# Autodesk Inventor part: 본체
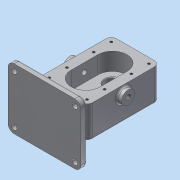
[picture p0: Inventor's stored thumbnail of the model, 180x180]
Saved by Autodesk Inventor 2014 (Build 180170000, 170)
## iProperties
Created: 2026-10
Part Number: 본체
Material: 알루미늄 6061
Document SubType Name: Modeling
Designer: dg
Density: 2.71 g/cm^3
Appearance: 알루미늄 - 평지
Mass: 1478.46 g
Surface Area: 818.031 cm^2
Volume: 545.557 cm^3
Author: dg
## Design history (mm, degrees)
sketch "스케치1"
  geometry: L1 (-40, 60)-(40, 60); L2 (40, 60)-(40, -60); L3 (40, -60)-(-40, -60); L4 (-40, -60)-(-40, 60); 3 further points
  constraints: 8 end point, 2 midpoint, 2 parallel, 1 horizontal, 1 horizontal alignment, 1 perpendicular, 1 vertical alignment
  dimensions: "d0" = 80 distance of L1.start L1.end; "d1" = 120 distance of L1.end L2.end
extrude "돌출1" new body sketch "스케치1" stored distance "d2" = 53; taper "d3" = 0 deg
sketch "스케치2"
  geometry: L1 (-40, 60)-(-40, -60) reference; L2 (0, 22)-(0, -22); L3 (-24, 22)-(-24, -22); L4 (24, -22)-(24, 22); A1 r 24 centre (0, 22) between (24, 22) and (-24, 22); A2 r 24 centre (0, -22) between (-24, -22) and (24, -22); 2 further points
  constraints: 8 end point, 4 point on circle, 4 tangent, 2 centre point, 2 parallel, 1 coincident, 1 midpoint
  dimensions: "d4" = 48 distance between parallel lines of L4 L3; "d5" = 44 distance of L4.start L4.end
extrude "돌출2" cut sketch "스케치2" distance "d6" = 29; taper "d7" = 0 deg
node "작업 평면1"
sketch "스케치3"
  geometry: L1 (-20, 70)-(100, 70); L2 (100, 70)-(100, -30); L3 (100, -30)-(-20, -30); L4 (-20, -30)-(-20, 70); L5 (0, 53)-(80, 53) reference; L6 (0, 53)-(0, 0) reference; L7 (80, 0)-(0, 0) reference; L8 (80, 0)-(80, 53) reference; L9 (0, 53)-(80, 53) reference; 1 further point
  constraints: 8 end point, 2 parallel, 1 horizontal, 1 perpendicular
  dimensions: "d9" = 100 distance of L3.end L1.start; "d10" = 120 distance of L2.end L3.end; "d25" = 17 distance between parallel lines of L1 L5; "d26" = 20 distance between parallel lines of L2 L8
extrude "돌출3" join sketch "스케치3" distance "d11" = 10; taper "d12" = 0 deg
sketch "스케치4"
  geometry: L1 (-60, 26.5)-(-60, -26.5) reference; L2 (-80, -43.5)-(-80, 56.5) reference; L3 (-57, 13.221)-(-80, 26.5); L4 (-57, -13.221)-(-80, -26.5); L5 (-57, 13.221)-(-57, -13.221); L6 (-80, 26.5)-(-80, -26.5); 3 further points
  constraints: 8 end point, 2 horizontal alignment, 2 midpoint, 2 point on line, 1 collinear, 1 parallel
  dimensions: "d13" = 53 distance of L4.end L3.end; "d14" = 60 deg angle of L2 L3; "d15" = 3 distance between parallel lines of L5 L1
extrude "돌출4" join sketch "스케치4" stored distance "d16" = 48; taper "d17" = 0 deg
sketch "스케치5"
  geometry: A1 r 24 centre (0, -22) between (-24, -22) and (24, -22) reference; A2 r 24 centre (0, 22) between (24, 22) and (-24, 22) reference; 1 further point
hole "구멍1" sketch "스케치5" at (0, 22), (0, -22) diameter "d18" = 25; stored, may be unused: countersink angle "d22" = 90 deg, drill point angle "d24" = 0 deg; dims "d19" = 6, "d20" = 4, "d21" = 2, "d23" = 15
sketch "스케치6"
  geometry: C1 r 12.5 at (0, 22) reference; C2 r 19 at (0, 22); 1 further point
  constraints: 1 centre point, 1 coincident
  dimensions: "d27" = 38 diameter of C2
extrude "돌출5" join sketch "스케치6" distance "d28" = 17; taper "d29" = 0 deg
sketch "스케치7"
  geometry: C1 r 19 at (0, 0) reference; 1 further point
hole "구멍2" sketch "스케치7" at (0, 0) diameter "d30" = 17; stored, may be unused: countersink angle "d34" = 90 deg, drill point angle "d36" = 0 deg; dims "d31" = 6, "d32" = 28, "d33" = 7.3, "d35" = 15
sketch "스케치8"
  geometry: L1 (0, 0)-(0, 120) reference; L2 (70, -30)-(-30, -30) reference; C1 r 11 at (14, 60); 1 further point
  constraints: 1 centre point
  dimensions: "d37" = 14 distance from line of L1 C1.centre; "d38" = 22 diameter of C1; "d39" = 90 distance from line of L2 C1.centre
extrude "돌출6" join sketch "스케치8" distance "d40" = 8; taper "d41" = 0 deg
sketch "스케치9"
  geometry: C1 r 11 at (-14, 60) reference; C2 r 11 at (-14, 60); 1 further point
  constraints: 1 centre point, 1 coincident, 1 concentric
extrude "돌출7" join sketch "스케치9" distance "d42" = 8; taper "d43" = 0 deg
hole "구멍3" diameter "d46" = 8; stored, may be unused: countersink angle "d52" = 90 deg, drill point angle "d54" = 118 deg; dims "d44" = 10, "d45" = 10, "d47" = 9, "d48" = 0.62479, "d49" = 7.985, "d50" = 28, "d51" = 7.3, "d53" = 30
hole "구멍4" diameter "d57" = 8; stored, may be unused: countersink angle "d63" = 90 deg, drill point angle "d65" = 118 deg; dims "d55" = 10, "d56" = 10, "d58" = 9, "d59" = 0.62479, "d60" = 7.985, "d61" = 28, "d62" = 7.3, "d64" = 30
sketch "스케치10"
  geometry: A1 r 24 centre (0, -22) between (-24, -22) and (24, -22) reference; A2 r 24 centre (0, 22) between (24, 22) and (-24, 22) reference; 9 further points
  constraints: 6 horizontal alignment, 6 vertical alignment
  dimensions: "d66" = 62 distance of point (31, 51) point (-31, 51); "d67" = 29 distance of point (-31, 22) point (-31, 51); "d68" = 29 distance of point (-31, -51) point (-31, -22); "d69" = 31 horizontal distance of A1.centre point (-31, -51)
hole "구멍5" sketch "스케치10" at (-31, 51), (-31, 22), (31, 22), (31, 51), (31, -22), (-31, -22), (-31, -51), (31, -51) diameter "d70" = 4.134; stored, may be unused: countersink angle "d74" = 90 deg, drill point angle "d76" = 118 deg; dims "d71" = 10, "d72" = 28, "d73" = 7.3, "d75" = 12
fillet "모깎기1" dims "d77" = 10
sketch "스케치11"
  geometry: A1 r 10 centre (-10, 60) between (-10, 70) and (-20, 60) reference; A2 r 10 centre (-10, -20) between (-20, -20) and (-10, -30) reference; A3 r 10 centre (90, -20) between (90, -30) and (100, -20) reference; A4 r 10 centre (90, 60) between (100, 60) and (90, 70) reference; 1 further point
hole "구멍6" sketch "스케치11" at (-10, 60), (-10, -20), (90, -20), (90, 60) diameter "d78" = 9; stored, may be unused: countersink angle "d82" = 82 deg, drill point angle "d84" = 0 deg; dims "d79" = 10, "d80" = 3.023, "d81" = 7.3, "d83" = 12
chamfer "모따기1" distance "d85" = 0.7; stored, may be unused: second distance "d86" = 2, angle "d87" = 30 deg
fillet "모깎기2" dims "d88" = 0.5
fillet "모깎기3" dims "d89" = 9
fillet "모깎기4" dims "d90" = 3
fillet "모깎기5" dims "d91" = 3
chamfer "모따기2" distance "d92" = 1; stored, may be unused: second distance "d93" = 2, angle "d94" = 30 deg
sketch "스케치12"
  geometry: L1 (-10, -30)-(90, -30) reference; 2 further points
  constraints: 1 vertical alignment, 1 other
  dimensions: "d95" = 10 distance from line of L1 point (40, -20)
feature "엠보싱1" sketch "스케치12" dims "d0" = 80, "d1" = 120, "d96" = 0.5, "d97" = 0
node "솔리드1"
node "투영된 루프1"
